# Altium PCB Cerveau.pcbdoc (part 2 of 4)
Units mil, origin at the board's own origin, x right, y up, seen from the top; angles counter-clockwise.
Board outline 3985.6 x 3546.5 mil, 2 copper layers (Top Layer, Bottom Layer), stack 62.2 mil thick; 170 components, 173 nets, 734 pads, 576 vias.
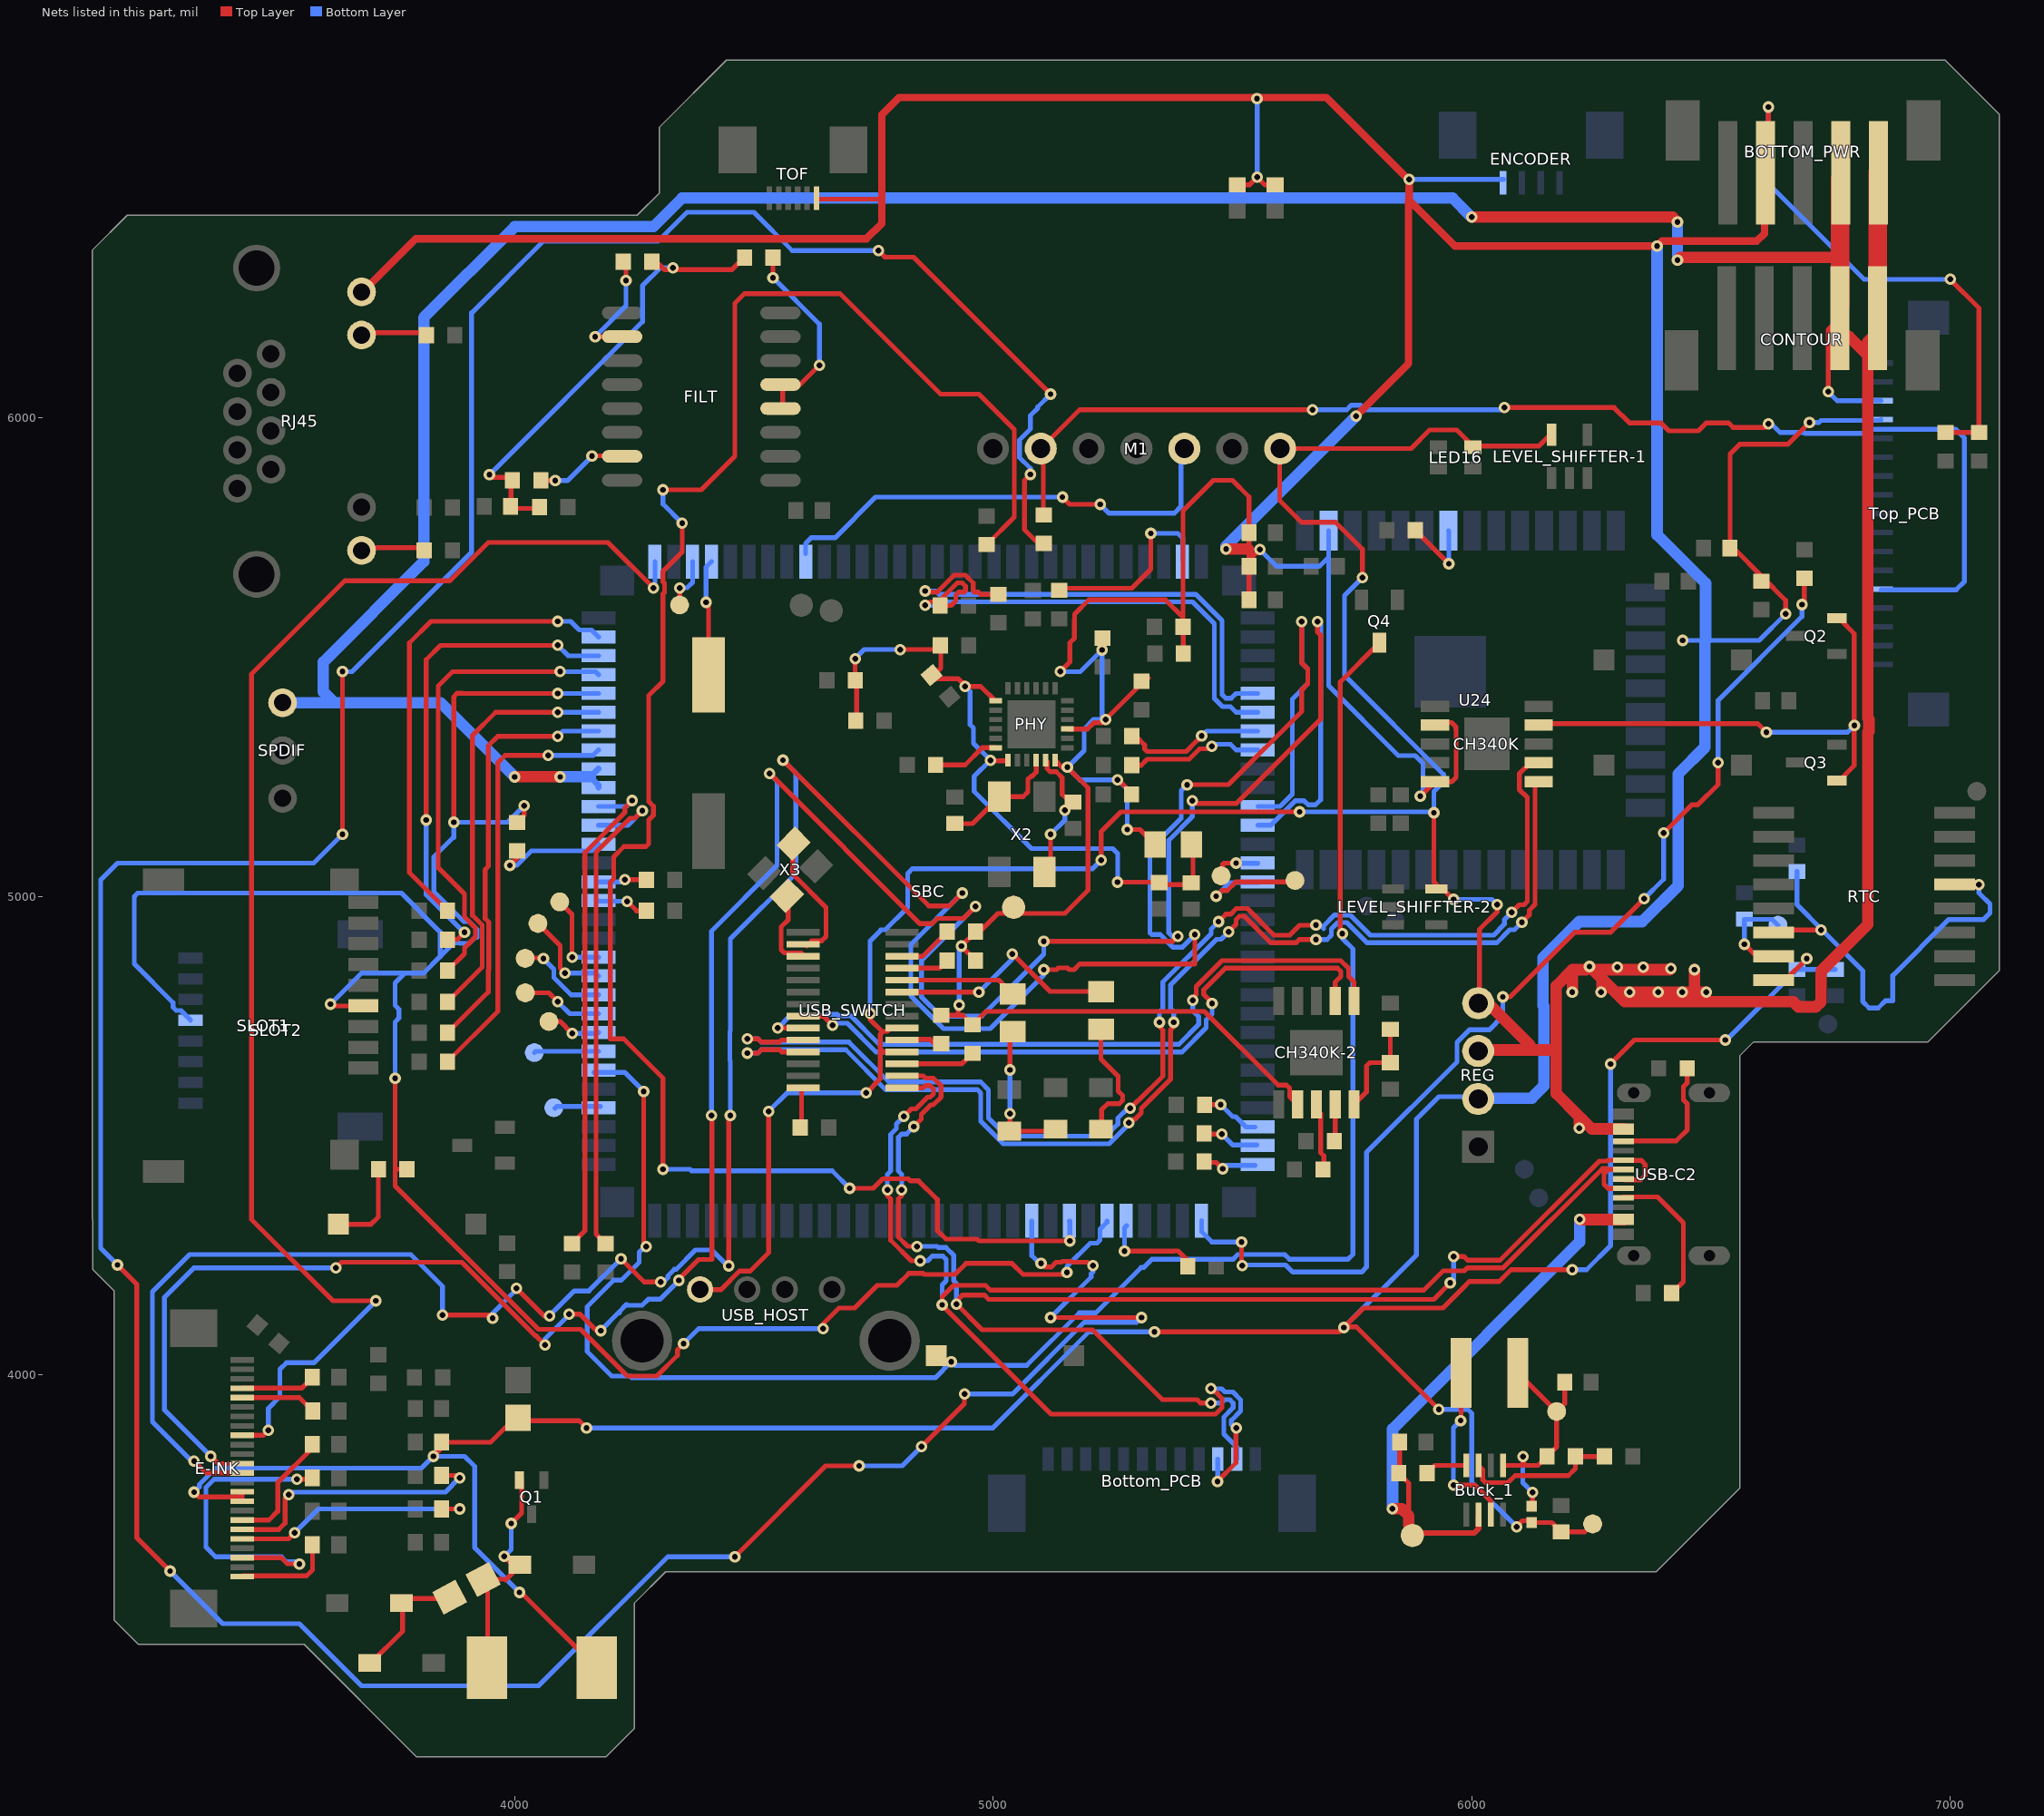
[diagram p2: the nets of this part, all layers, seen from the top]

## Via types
v1: diameter 24, hole 12, Top Layer to Bottom Layer, 576 vias

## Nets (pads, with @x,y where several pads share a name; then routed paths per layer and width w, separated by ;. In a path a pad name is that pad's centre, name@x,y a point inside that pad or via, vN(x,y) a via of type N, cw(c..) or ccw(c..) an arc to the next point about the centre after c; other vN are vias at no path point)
3V3: 3V3.1 BOTTOM_PWR.2 C7.1 C8.2 C9.1 C10.2 C11.1 C18.2 C28.1 C29.2 C33.2 C35.1 C36.2 CH340K-2.7 CH340K.7 CH340K.10 E-INK.15 E-INK.16 ENCODER.1 L2.2 L3.1 P-SCL.2 P-SDA.2 PHY.6 PHY.9 R9.1 R10.1 R11.2 R12.2 R13.2 R14.2 R15.2 R16.2 R21.2 R32.2 R41.2 REG.2 RJ45.9 RSC_3V3.1 RTC.16 TOF.1 Top_PCB.14 U24.2 | length 20598.6
  Top Layer w10: v1(3330,3755) 3340,3745 3421.8,3745 E-INK.15@3430.7,3753.9 ; E-INK.16@3430.7,3736.1 E-INK.15@3430.7,3753.9 ; E-INK.15@3430.7,3755.8 E-INK.15@3430.7,3753.9 ; v1(3830,3830) 3847.6,3847.6 C18.2@3847.6,3857.6 ; C18.2@3847.6,3859.4 C18.2@3847.6,3860 ; C18.2@3848.2,3859.4 3949.7,3859.4 C33.2@3998.4,3908.1 ; C33.2@4002.3,3904.3 4134.7,3904.3 v1(4150.1,3888.9) ; v1(4010,3545.4) 4013.1,3545.4 L3.1@4160.3,3398.2 ; TOF.1@4630.2,6457.7 4762.1,6457.7 4763.8,6459.4 ; R15.2@4891.5,4751.7 4926.4,4751.7 ; v1(4928.8,4773) 4926.4,4770.6 4926.4,4751.7 ; R14.2@4963.2,4866.3 4963.2,4866.6 v1(4933.5,4896.3) 4963.2,4926 R13.2@4963.2,4926.3 4971.8,4926.3 5010.2,4964.7 5019,4964.7 ; 3V3.1@5042.7,4997.2 5047.1,4992.8 5019,4964.7 ; PHY.6@5129.2,5284.9 5144.1,5270 v1(5155,5270) 5198.1,5226.9 5198.1,5013.1 5149.7,4964.7 5019,4964.7 ; v1(5140,5470) 5160,5490 5160,5530 5169.8,5539.8 5169.8,5578.4 5170,5578.6 5170,5590 5200,5620 5360,5620 5396.5,5583.5 ; PHY.9@5155.1,5350.2 5155.3,5350 5196.9,5350 5209.9,5363 5228,5363 v1(5235,5370) 5310,5445 R10.1@5310,5449.7 ; v1(5227.4,5515.4) 5228.2,5516.2 R41.2@5228.2,5545.3 ; v1(5259.9,5244) 5261.3,5244 R9.1@5292.3,5213 ; v1(5280,5140) 5306.9,5140 L2.2@5338.3,5108.6 ; R10.1@5319.5,5461.5 R10.1@5324.3,5456.7 ; v1(5337,4090) 5723.7,4090 v1(5732.6,4099) 5773.7,4140 5940,4140 5981.6,4181.6 5981.6,4181.8 5995,4195.2 6057.1,4195.2 6081.9,4220 v1(6210,4220) ; R12.2@5397,5507.8 5397,5563.2 R11.2@5396.5,5563.8 5396.5,5583.5 ; C7.1@5510,6487.6 5535.9,6487.6 v1(5551.7,6503.4) 5567.6,6487.4 C8.2@5589.2,6487.4 ; C9.1@5534.7,5620.3 C10.2@5534.7,5690.3 ; v1(5557.2,5725.3) 5534.7,5702.7 C11.1@5534.7,5760.3 5534.7,5835.3 5500,5870 5460,5870 5396.5,5806.5 5396.5,5583.5 ; CH340K-2.7@5636,4565.3 5619.5,4581.9 5619.5,4599.4 5613,4605.8 5595.5,4605.8 5441.4,4760 4984.8,4760 R16.2@4956.5,4731.7 4936.5,4751.7 4926.4,4751.7 ; v1@5735.1,4100.4 5758.8,4100.4 v1(5931.2,3928) ; v1(5892.6,5209.4) 5917.2,5233.9 CH340K.10@5917.2,5239.1 ; CH340K.7@5918.4,5363.7 5957.7,5363.7 5967.1,5354.3 ; CH340K.10@5926.7,5239.7 5957.7,5239.7 5967.2,5249.2 5967.2,5349.4 5967.2,5354.2 5967.1,5354.3 ; 5967.1,5349.4 5967.1,5354.3 ; v1(6093.7,3682.7) 6106,3695.1 R32.2@6123.9,3695.1 ; R32.2@6125.1,3691.5 6167.5,3691.5 C29.2@6186.9,3672 6236.1,3672 RSC_3V3.1@6252.7,3688.6 ; v1(6290,4650) 6340,4700 v1(6530,4700) ; C28.1@6539.3,5727.9 6540,5728.6 6540,5925 6560,5945 6660.1,5945 v1(6705.8,5990.7) ; C28.1@6550,5725.6 R21.2@6607.6,5668 ; R21.2@6608.8,5666.2 6656.1,5618.9 v1(6656.1,5590.7) ; BOTTOM_PWR.2@6613.8,6512.6 6620,6518.7 v1(6620,6650) ; RTC.16@6631,4825 6655,4825 v1(6700,4870) ; P-SCL.2@6990,5969.7 P-SDA.2@7060,5969.7 7060,6230 v1(7000,6290)
  Top Layer w15.7: RJ45.9@3681.1,6262.5 3793.4,6374.8 4735.4,6374.8 4767.1,6406.5 4767.1,6634.2 4803,6670.1 5696,6670.1 5869,6497.1 5869,6455.3 5964.8,6359.5 v1(6387.4,6359.5) 6397.8,6370 6596,6370 6611.8,6385.7 BOTTOM_PWR.2@6611.8,6489 ; v1(5758.1,6003.9) 5868,6113.8 5868,6454.9
  Top Layer w23.6: v1(5486.6,5726.1) 5532.5,5726.1 5533.4,5725.2
  Bottom Layer w10: v1(3330,3755) 3341,3766 3341,3770.8 3375.2,3805.1 3805.1,3805.1 v1(3830,3830) 3895.3,3830 3916.7,3808.6 3916.7,3638.6 v1(4010,3545.4) ; v1(4150.1,3888.9) 4998.9,3888.9 5200,4090 v1(5337,4090) ; v1(4928.8,4773) 4928.8,4891.6 v1(4933.5,4896.3) ; v1(5140,5470) 5182,5470 v1(5227.4,5515.4) 5227.4,5377.5 v1@5233.3,5371.6 ; v1(5235,5370) 5210,5370 5190,5350 5190,5305 v1(5155,5270) 5181,5244 v1(5259.9,5244) 5280,5223.9 v1(5280,5140) ; v1(5551.3,6667.5) 5551.7,6667 v1(5551.7,6503.4) ; v1(5557.2,5725.3) 5592.2,5690.3 5682.2,5690.3 5701.1,5709.2 U24.2@5701.1,5764.6 ; 5700.8,5707.9 5700.8,5440.3 5846.5,5294.6 5881.8,5294.6 5898,5278.4 5898,5214.7 v1(5892.6,5209.4) ; v1(5732.6,4099) 5884.6,4251 5884.6,4534.9 5931.6,4581.8 REG.2@6007.1,4581.8 ; v1(5869.3,6499.1) ENCODER.1@6066.8,6499.1 ; v1(5931.2,3928) 5992,3928 6000,3920 6000,3776.4 v1(6093.7,3682.7) ; v1(6210,4220) 6240,4220 6290,4270 v1(6290,4650) ; v1(6440.8,5535.2) 6488.7,5535.2 6600.6,5535.2 v1(6656.1,5590.7) ; v1(6530,4700) 6532.4,4700 C36.2@6680,4847.6 ; v1(6620,6650) 6620,6490 6820,6290 v1(7000,6290) ; v1(6700,4870) 6700,4867.6 C36.2@6680,4847.6 ; v1(6705.8,5990.7) 6725.7,5990.7 6730,5995 6853.4,5995 Top_PCB.14@6855.3,5996.9 ; C35.1@6760,4847.6 C36.2@6680,4847.6
  Bottom Layer w23.6: v1(5486.6,5726.1) 5486.6,5732.3 v1(5758.1,6003.9)
  Bottom Layer w24.1: REG.2@6007.1,4579.4 6008.1,4578.4 6126.2,4578.4 ; 6126.2,4579.5 6150.8,4604.1 6150.8,4770.3 ; 6148.9,4772.1 6148.9,4871.6 6224.8,4947.5 6356.2,4947.5 6431.6,5022.9 6431.6,5256.2 6487.3,5311.9 6487.3,5533.1 ; v1(6387.4,6359.5) 6387.4,5755.8 6488.7,5654.5 6488.7,5535.2
3V3_MOD: R22.2 R45.2 SBC.66 SBC.116 SLOT1.4 SLOT2.4 | length 4873.3
  Top Layer w10: v1(3615,4775) 3618.7,4771.3 SLOT1.4@3683.7,4771.3 ; v1(3750,4620) 3750,4429 ; R22.2@3774.7,4430 3751,4430 3750,4429 ; v1(3872.9,5155) 3872.9,5417.9 3880,5425 3890,5425 3890.6,5424.4 v1(4090,5424.4) ; R45.2@4005,5154.7 4020,5169.7 v1(4020,5190) ; 4049.6,4095.4 3750,4395 3750,4429 ; 4049.6,4095.5 4137.7,4095.5 4235.7,3997.5 4296.9,3997.5 4340.3,4040.9 4340.3,4052.8 v1(4352.9,4065.5) ; v1(4644.4,4096.8) 4644.4,4106.7 4677.6,4140 4710.1,4140 4757.5,4187.4 4798.8,4187.4 4823.6,4212.2 4853.4,4212.2 4855.6,4210 4920,4210 4943,4233 5039.5,4233 5062.5,4210 5149.6,4210 v1(5154,4214.4)
  Bottom Layer w10: SLOT2.4@3322.7,4741.5 3302.4,4761.8 3292.6,4761.8 3286.1,4768.3 3286.1,4778.1 3205,4859.2 3205,5000 3212.1,5007.1 3763.2,5007.1 3844.3,4926 3844.3,4874.3 ; v1(3615,4775) 3680,4840 3770.7,4840 ; v1(3750,4620) 3750,4737.5 3758,4745.5 3758,4764.5 3750,4772.5 3750,4819.3 3770.7,4840 ; 3871.9,5123.5 3831.2,5082.9 3831.2,5010.1 3893.3,4948 3904.5,4948 3921.3,4931.2 3921.3,4914.7 ; 3872.9,5123.5 v1(3872.9,5155) 3985,5155 v1(4020,5190) ; 3918,4915.5 3904.5,4902 3885.5,4902 3884.6,4902.9 3872.9,4902.9 3844.3,4874.3 ; v1(4090,5424.4) SBC.116@4175,5424.4 ; v1(4352.9,4065.5) 4384.3,4096.8 v1(4644.4,4096.8) ; v1(5154,4214.4) 5154,4226.8 5202.8,4275.6 5217,4275.6 5223.4,4282.1 5223.4,4305 5238,4319.6 SBC.66@5238,4322 ; 3770.7,4840 3810,4840 3844.3,4874.3
5V: 5V.1 BOTTOM_PWR.4 BOTTOM_PWR.5 Buck_1.2 C31.1 CONTOUR.1 CONTOUR.2 LED16.4 LEVEL_SHIFFTER-1.5 LEVEL_SHIFFTER-2.5 M1.7 R29.1 REG.3 REG.4 SBC.111 SBC.112 SPDIF.3 Top_PCB.15 USB-C2.A4B9 USB-C2.B4A9 USB_HOST.1 USB_SWITCH.18 USB_SWITCH.20 | length 14819.2
  Top Layer w10: USB_HOST.1@4387.5,4178.5 4431.4,4178.5 4469.9,4217 4492,4217 4530.7,4255.7 v1(4530.7,4551) ; v1(4734.7,4589.4) 4763.8,4618.5 4763.8,4681.9 ; v1(4742.8,4755.6) 4742.8,4742.6 4768.8,4716.6 ; USB_SWITCH.20@4786.7,4726 4778.8,4718 4770.2,4718 4768.8,4716.6 ; USB_SWITCH.18@4811.1,4674.6 4771.1,4674.6 4763.8,4681.9 ; v1(5225.8,5076.1) 5225.8,5135.8 5266.9,5176.9 v1(5640.4,5176.9) ; v1(5771.4,5666.4) 5771.4,5726.3 5715.5,5782.2 5644.1,5782.2 5598.5,5827.8 5598.5,5936.3 5873.5,5936.3 5912,5974.9 5968.8,5974.9 LED16.4@6002.6,5941.1 ; R29.1@5849.4,3796.7 C31.1@5849.4,3859.6 ; R29.1@5849.9,3792 5868.5,3773.4 5868.5,3705.4 ; 5V.1@5868.5,3686.4 5875.5,3679.4 5V.1@5875.5,3672.7 ; v1(5921,5174.9) 5921,5030.6 LEVEL_SHIFFTER-2.5@5933.7,5018 ; LEVEL_SHIFFTER-2.5@5941.9,5014 v1(5961.9,4994) ; LED16.4@6007.4,5941.2 6139.8,5941.2 LEVEL_SHIFFTER-1.5@6164.7,5966.1 ; REG.4@6016.2,4776.5 6016.2,4780.1 6016.2,4931.2 6053.3,4968.3 v1(6053.3,4983.1) ; v1(6745,6055) 6745,6184.7 CONTOUR.2@6769.2,6208.9 ; 4763.8,4681.9 4763.8,4711.6 4768.8,4716.6
  Top Layer w11.8: 5V.1@5883.5,3663.9 5889.4,3669.9 6004.7,3669.9 ; 6005.6,3670.4 6014.1,3679 Buck_1.2@6014.1,3706.1
  Top Layer w23.6: v1(4000,5250) v1(4095,5250) ; v1(6000,6420) 6420,6420 v1(6430,6410) ; v1(6430,6330) 6435.9,6335.9 6769.7,6335.9
  Top Layer w24.1: v1(5834.5,3720.3) 5853.6,3720.3 5868.5,3705.4 5V.1@5868.5,3686.4 ; REG.4@6009,4780.1 REG.4@6016.2,4780.1 ; REG.3@6016.6,4680.2 6017.6,4679.3 6176.6,4679.3 ; REG.4@6030.9,4780.1 6121.3,4689.7 ; v1(6210,4800) 6210.5,4800.5 6210.5,4846.9 ; v1@6224.8,4517 6224.8,4539.8 6176.6,4588 6176.6,4679.3 ; v1(6225.5,4325) 6226.1,4324.5 USB-C2.A4B9@6319.3,4324.5 ; 6229.9,4535.3 6251,4514.1 USB-C2.B4A9@6318.1,4514.1 ; v1(6246.2,4853.8) 6239.3,4846.9 6210.5,4846.9 ; v1(6270,4800) 6272.4,4802.4 6272.4,4827.6 ; v1(6304.6,4852.1) v1@6309.8,4846.9 ; v1(6358.3,4852.5) v1@6363.9,4846.9 ; v1(6416.2,4849.1) 6414,4846.9 v1@6363.9,4846.9 ; v1(6465.3,4847) 6465.3,4801.2 6464.1,4800 ; v1(6490,4800) 6464.1,4800 ; CONTOUR.2@6772.3,6170.4 6788.4,6170.4 6821.7,6137.1 ; 6827.4,6137.1 6827.4,5372.5 6829.9,5370.1 6829.9,5345.2 6827.4,5342.8 6827.4,4941.1 6730,4843.6 6730,4780 6719.3,4769.3 6682.6,4769.3 6671.8,4780 6320,4780 6300,4800 ; 6827.4,6159 CONTOUR.1@6851.2,6182.8 ; 6176.6,4679.3 6176.6,4813 6210.5,4846.9 ; 6272.4,4827.6 6253.1,4846.9 v1@6309.8,4846.9 ; 6272.4,4827.6 6300,4800 ; 6300,4800 v1(6330,4800) v1(6390,4800) v1(6440,4800) 6464.1,4800 ; v1@6309.8,4846.9 v1@6363.9,4846.9
  Top Layer w39.4: CONTOUR.2@6769.7,6235.2 6769.7,6335.9 BOTTOM_PWR.4@6769.7,6499.7 ; CONTOUR.1@6848.4,6192.7 BOTTOM_PWR.5@6848.4,6515
  Bottom Layer w10: v1(4530.7,4551) 4569.1,4589.4 v1(4734.7,4589.4) ; v1(4742.8,4755.6) 4742.8,4907.1 4766.2,4930.5 ; 4765.1,4930.5 4766.2,4930.5 ; 4821,4977.2 4774.3,4930.5 4766.2,4930.5 ; 4821.2,4977 4821.2,5048.1 4831.2,5058.1 5207.9,5058.1 v1(5225.8,5076.1) ; v1(5640.4,5176.9) 5919,5176.9 v1(5921,5174.9) 5921,5219.6 5941.3,5239.8 5941.3,5254.9 5734,5462.2 5734,5629 v1(5771.4,5666.4) ; v1(5961.9,4994) 6042.4,4994 v1(6053.3,4983.1) ; v1(6745,6055) 6763.8,6036.2 Top_PCB.15@6855.3,6036.2
  Bottom Layer w12.6: SBC.111@4175,5227.6 4175,5233.1 4158.1,5250 SBC.112@4175,5266.9
  Bottom Layer w23.6: SPDIF.3@3515,5405 3622.7,5405 ; v1(4000,5250) 3845,5405 3622.7,5405 ; v1(4095,5250) 4158.1,5250 ; v1(6000,6420) 5960,6460 4350,6460 4290,6400 4000,6400 3810,6210 3810,5700 3600,5490 3600,5427.7 3622.7,5405 ; v1(6430,6330) v1(6430,6410)
  Bottom Layer w24.1: v1(5834.5,3720.3) 5834.5,3887 6225.5,4278 v1(6225.5,4325)
  other v1: 6224.7,4515.7
$1N2333: R2.2 USB-C2.A5 | length 304.6
  Top Layer w10: USB-C2.A5@6316.7,4371.9 6388.1,4371.9 6442.1,4317.9 6442.1,4195.1 R2.2@6418.1,4171
$1N2334: R1.2 USB-C2.B5 | length 272.3
  Top Layer w10: USB-C2.B5@6323,4489.1 6427.3,4489.1 6450.6,4512.4 6450.6,4566.6 6442.1,4575 6442.1,4602.2 6450.6,4610.7 R1.2@6450.6,4640.4
$1N52006: Buck_1.3 L1.1 | length 361.4
  Top Layer w10: v1(5961.9,3769.6) 6006.9,3769.6 6039.7,3736.8 Buck_1.3@6039.7,3708.4 ; v1(5976.9,3904.6) 5977.9,3905.5 L1.1@5977.9,4004.6
  Bottom Layer w10: v1(5961.9,3769.6) 5961.9,3889.6 v1(5976.9,3904.6)
$1N52007: Buck_1.5 C30.1 L1.2 R30.2 R32.1 REG_OUT.1 | length 519.8
  Top Layer w10: Buck_1.5@6065.3,3810.8 6113.3,3810.8 ; L1.2@6096,4004.6 6176.9,3923.6 REG_OUT.1@6177.5,3923.6 ; v1(6106.9,3829.6) 6106.9,3817.2 6113.3,3810.8 ; R32.1@6125.1,3725.5 6126.9,3727.4 v1(6126.9,3754.6) ; C30.1@6194.4,3984.6 6194.4,3940.5 REG_OUT.1@6177.5,3923.6 ; 6113.3,3810.8 6138.4,3810.8 R30.2@6157.3,3829.6 6177.5,3849.8 REG_OUT.1@6177.5,3923.6
  Bottom Layer w10: v1(6106.9,3829.6) 6106.9,3774.6 v1(6126.9,3754.6)
$1N52011: Buck_1.7 R30.1 R31.1 | length 327.9
  Top Layer w10: Buck_1.7@6014.1,3810.8 6022.8,3802.1 6022.8,3781.2 6029.3,3774.8 6075.8,3774.8 6090.6,3789.6 6201.9,3789.6 6216.6,3804.2 R30.1@6216.6,3829.6 R31.1@6277.3,3829.6
$1N52013: Buck_1.8 R29.2 | length 88.6
  Top Layer w10: R29.2@5906.6,3794.6 5922.8,3810.8 Buck_1.8@5988.5,3810.8
$1N100879: FILT.4 FILT.5 R33.1 | length 408
  Top Layer w10: v1(4539.8,6293.3) 4539.8,6326.9 R33.1@4541.4,6328.5 ; FILT.5@4553.6,6065.6 FILT.5@4560,6065.6 ; FILT.4@4560,6018.4 FILT.5@4560,6065.6 ; v1(4636.9,6110.4) 4592.1,6065.6 FILT.5@4560,6065.6
  Bottom Layer w10: v1(4539.8,6293.3) 4636.9,6196.2 v1(4636.9,6110.4)
$1N101081: FILT.15 R34.1 | length 178.7
  Top Layer w10: R34.1@4054.8,5870.3 4055.9,5869.2 v1(4084.7,5869.2) ; v1(4161.5,5920.4) 4162,5920.9 FILT.15@4211.6,5920.9
  Bottom Layer w10: v1(4084.7,5869.2) 4110.3,5869.2 v1(4161.5,5920.4)
$1N101084: FILT.10 R35.1 | length 230.9
  Top Layer w10: v1(4168,6170) 4211.9,6170 FILT.10@4213.4,6168.5 ; R35.1@4223.8,6324.5 4232.6,6315.7 v1(4232.6,6287.7)
  Bottom Layer w10: v1(4168,6170) 4232.6,6234.6 v1(4232.6,6287.7)
$1N101107: C26.2 R33.2 R34.2 R35.2 R36.2 | length 969.8
  Top Layer w10: v1(3947.3,5881.5) 3953,5875.8 R34.2@3994,5875.8 ; R34.2@3992.3,5867.1 3992.3,5817.5 3998.7,5811.1 R36.2@4056.3,5811.1 ; R35.2@4298.4,6324.9 4313.4,6310 v1@4334.8,6310 ; v1(4330.8,6314) v1@4334.8,6310 ; R33.2@4475.4,6331.6 4453.8,6310 v1@4334.8,6310
  Bottom Layer w10: v1(3947.3,5881.5) 4267,6201.2 4267,6276.4 4304.6,6314 v1(4330.8,6314)
$1N108144: R24.2 RJ45.10 | length 132.5
  Top Layer w10: RJ45.10@3686.9,6178.4 3817.7,6178.4 R24.2@3818.9,6177.2
$1N108803: PHY.24 R7.2 | length 140
  Top Layer w10: R7.2@4879.7,5275 4941.3,5275 4977.1,5310.8 PHY.24@5004.9,5310.8
$1N111794: R25.1 RJ45.12 | length 129.9
  Top Layer w10: RJ45.12@3680.8,5715.3 3694.7,5729.2 R25.1@3804.9,5729.2
$1N122388: C23.1 E-INK.22 | length 689.9
  Top Layer w10: E-INK.22@3430.7,3618 3512,3618 3525,3605 v1(3550,3605) ; v1(3545,3782.1) 3574.5,3782.1 C23.1@3577.4,3785
  Bottom Layer w10: v1(3545,3782.1) 3372.1,3782.1 3355,3765 3355,3640 3375,3620 3512.5,3620 3523,3609.5 3545.5,3609.5 v1(3550,3605)
$1N122658: C32.2 L3.2 Q1.2 U21.2 | length 502.2
  Top Layer w10: L3.2@3935.8,3383.6 3943.4,3391.2 C32.2@3943.4,3573.1 ; C32.2@3943.4,3584.1 C32.2@3943.4,3573.1 ; v1(3978.3,3620.6) 3992.8,3606 U21.2@4013.4,3606 ; 3979.5,3573.1 C32.2@3943.4,3573.1 ; 3980.7,3571.4 U21.2@4011.8,3602.5 ; v1(3992.8,3689.5) 4014.7,3711.3 Q1.2@4014.7,3782.8
  Bottom Layer w10: v1(3978.3,3620.6) 3992.8,3635.1 v1(3992.8,3689.5)
$1N122770: C32.1 U22.2 U23.1 | length 259.9
  Top Layer w10: U22.2@3697.9,3396.3 3765.8,3464.2 U23.1@3765.8,3524.4 ; U23.1@3763.5,3523 3773.3,3532.8 C32.1@3863.1,3532.8
$1N123105: C16.2 E-INK.4 | length 156.1
  Top Layer w10: E-INK.4@3430.7,3972.3 3554.8,3972.3 C16.2@3577.4,3995
$1N123149: C17.2 E-INK.5 | length 158.6
  Top Layer w10: E-INK.5@3430.7,3952.6 3549.8,3952.6 C17.2@3577.8,3924.7
$1N123431: C25.1 E-INK.24 | length 205
  Top Layer w10: E-INK.24@3430.7,3578.6 3432.1,3580 3565,3580 3577.4,3592.4 C25.1@3577.4,3645
$1N123445: C21.1 E-INK.20 | length 517.6
  Top Layer w10: E-INK.20@3430.7,3657.4 3527.4,3657.4 v1(3540,3670) ; C21.1@3847.6,3720 v1(3885,3720)
  Bottom Layer w10: v1(3540,3670) 3590,3720 v1(3885,3720)
$1N123447: C20.1 E-INK.19 | length 576.1
  Top Layer w10: E-INK.19@3430.7,3677 3507,3677 3520,3690 3520,3742.1 v1(3527.9,3750) ; C20.1@3847.6,3790 3880,3790 v1(3885,3785)
  Bottom Layer w10: v1(3527.9,3750) 3527.9,3752.1 3525,3755 3855,3755 v1(3885,3785)
$1N123450: C19.1 E-INK.18 | length 251.9
  Top Layer w10: E-INK.18@3430.7,3696.7 3486.7,3696.7 3504.9,3714.9 3504.9,3774.9 3577.4,3847.4 C19.1@3577.4,3855
$1N137689: C5.2 PHY.4 X2.3 | length 254.8
  Top Layer w10: C5.2@4920,5152.4 4956.5,5152.4 X2.3@5012.8,5208.7 5062.6,5208.7 5072.6,5218.7 5072.6,5244.8 5079.1,5251.2 5081.2,5251.2 5090,5260 5090,5284.7 PHY.4@5089.8,5284.9
$1N137708: C6.1 PHY.5 X2.1 | length 291.3
  Top Layer w10: X2.1@5107.2,5051.3 5120,5064 v1(5120,5130) ; PHY.5@5109.5,5284.9 5112.7,5281.7 5112.7,5267.3 5119.1,5260.8 5131.7,5260.8 5144.2,5248.3 5144.2,5213.3 C6.1@5163.2,5194.1 ; v1(5150,5180) 5166.7,5196.7 C6.1@5166.7,5197.6
  Bottom Layer w10: v1(5120,5130) 5150,5160 v1(5150,5180)
$1N182029: R19.2 USB_SWITCH.14 | length 83.2
  Top Layer w10: R19.2@4599.4,4517.1 4599.4,4595.9 USB_SWITCH.14@4602.5,4599
$1N186429: USB_SWITCH.3 X3.3 | length 172.8
  Top Layer w10: X3.3@4571.7,4999.7 4571.7,4951.2 4557,4936.6 4557,4888.7 4563.4,4882.3 4599,4882.3 USB_SWITCH.3@4606.8,4874.5
$1N186434: USB_SWITCH.2 X3.1 | length 264.1
  Top Layer w10: X3.1@4580.9,5103.7 4580.9,5046.7 4650.5,4977.2 4650.5,4916.2 4641.5,4907.3 4621,4907.3 USB_SWITCH.2@4610.7,4897
$1N186463: C3.1 C4.2 L2.1 PHY.1 PHY.19 R3.1 R4.1 R5.2 R6.2 | length 1510.9
  Top Layer w10: R6.2@4710.3,5366.4 4714.8,5371 R3.1@4714.8,5452.3 ; R3.1@4711.2,5451.1 4711.2,5493.9 v1@4713.4,5496.2 ; v1(4805.5,5516.1) 4876.4,5516.1 R4.1@4890.6,5530.4 ; R4.1@4890.3,5529.6 4890.3,5477.5 4868.2,5455.4 4926.3,5455.4 v1@4940.4,5441.3 ; v1@4940.4,5446.7 v1@4940.4,5441.3 ; v1@4941.1,5439.1 4974.1,5439.1 PHY.19@5003.2,5410 ; v1@4941.1,5440.6 v1@4940.4,5441.3 ; v1(4994.2,5284.7) 4995.3,5283.6 PHY.1@5031.3,5283.6 ; v1(5260,5030) 5346.3,5030 C3.1@5347.2,5029.1 ; C3.1@5347.2,5024.7 5404.9,5024.7 C4.2@5409.9,5029.8 ; C4.2@5410,5029.8 5417.5,5037.1 L2.1@5417.5,5110
  Bottom Layer w10: v1(4711.6,5497.1) 4730.6,5516.1 v1(4805.5,5516.1) ; v1(4941.3,5439.1) 4951.7,5428.7 4951.7,5359.4 4958.6,5352.5 4958.6,5320.3 v1(4994.2,5284.7) 4960,5250.6 4960,5220 5080,5100 5250,5100 5260,5090 v1(5260,5030)
$1N186835: CH340K-2.8 R-RX2.1 | length 136.7
  Top Layer w10: CH340K-2.8@5674.5,4556.1 5684.5,4546.1 5684.5,4464.3 5691.1,4457.8 R-RX2.1@5691.1,4426.3
$1N186841: CH340K-2.9 R-TX2.1 | length 79
  Top Layer w10: R-TX2.1@5714.8,4484.8 5714.8,4560.9 CH340K-2.9@5716.9,4562.9
$1N186854: C1.2 C2.1 CH340K-2.10 | length 213.7
  Top Layer w10: CH340K-2.10@5754.1,4565.3 5780,4591.2 5780,4645.5 5787.1,4652.6 C1.2@5830,4652.6 C2.1@5830,4722.4
$1N187062: R16.1 USB_SWITCH.17 | length 156.5
  Top Layer w10: USB_SWITCH.17@4809.2,4650.1 4934.3,4650.1 R16.1@4956.5,4672.3
$1N187101: R13.1 USB_SWITCH.26 | length 115.8
  Top Layer w10: USB_SWITCH.26@4809.2,4875.1 4852.7,4875.1 R13.1@4903.8,4926.3
$1N187435: R15.1 USB_SWITCH.19 | length 86.5
  Top Layer w10: USB_SWITCH.19@4809.2,4700.1 4810.4,4701.3 4868.5,4701.3 4877.5,4692.3 R15.1@4891.5,4692.3
$1N187580: R14.1 USB_SWITCH.25 | length 101.3
  Top Layer w10: USB_SWITCH.25@4809.2,4850.1 4887.7,4850.1 R14.1@4903.8,4866.3
$1N187585: R18.1 USB_SWITCH.24 | length 243.2
  Top Layer w10: USB_SWITCH.24@4809.2,4825.1 5011.8,4825.1 R18.1@5040.5,4796.4
$1N187593: R17.2 USB_SWITCH.23 | length 487.8
  Top Layer w10: USB_SWITCH.23@4809.2,4800.1 v1(4970,4800.1) ; v1(5040,4880) 5118.6,4801.4 R17.2@5225.5,4801.4
  Bottom Layer w10: v1(4970,4800.1) 5040,4870.1 v1(5040,4880)
$1N196349: PORT-1.1 PORT-3.2 R18.2 | length 307.8
  Top Layer w10: v1(5035.2,4546.2) 5035.2,4509.5 PORT-3.2@5131.3,4509.5 ; v1(5035.2,4637.6) 5035.2,4716 R18.2@5038.9,4719.7
  Bottom Layer w10: v1(5035.2,4546.2) v1(5035.2,4637.6)
$1N196355: PORT-2.1 R17.1 | length 254.6
  Top Layer w10: R17.1@5225.3,4721.7 5225.3,4660.4 5261.1,4624.6 5261.1,4593.3 5270.5,4583.9 5270.5,4573.9 5263.5,4566.8 5239.2,4566.8 5226.3,4553.9 PORT-2.1@5226.3,4518.3
$1N217183: R20.2 U24.7 | length 169.1
  Top Layer w10: R20.2@5881.9,5765.3 5951.9,5695.3 v1(5952.2,5695.3)
  Bottom Layer w10: U24.7@5951.1,5764.6 5952.2,5763.5 v1(5952.2,5695.3)
$1N235786: R47.1 SBC.106 | length 102.1
  Top Layer w10: v1(4230,5035) R47.1@4275.3,5035
  Bottom Layer w10: SBC.106@4175,5030.7 4225.7,5030.7 v1(4230,5035)
$1N235788: R46.1 SBC.105 | length 109.1
  Top Layer w10: v1(4235,4990) 4255,4970 R46.1@4275.3,4970
  Bottom Layer w10: SBC.105@4175,4991.3 4176.3,4990 v1(4235,4990)
$1N236245: GPIO0_A1.1 SBC.3 | length 110.7
  Top Layer w10: GPIO0_A1.1@4344.7,5609.4 4344.7,5644.7 v1(4345,5645)
  Bottom Layer w10: v1(4345,5645) 4360,5645 4371.9,5656.9 SBC.3@4371.9,5700
$1N236288: SBC.101 TP5.1 | length 199.6
  Top Layer w10: TP5.1@4048.5,4943.7 4095,4897.2 4095,4850 v1(4105,4840)
  Bottom Layer w10: v1(4105,4840) 4168.9,4840 SBC.101@4175,4833.9
$1N236290: SBC.102 TP6.1 | length 181.3
  Top Layer w10: TP6.1@4094.1,4988.7 4120,4962.9 v1(4120,4873.2)
  Bottom Layer w10: v1(4120,4873.2) SBC.102@4175,4873.2
$1N236292: SBC.100 TP4.1 | length 187.9
  Top Layer w10: TP4.1@4024.5,4871.5 4055,4871.5 v1@4055.6,4872.2
  Bottom Layer w10: v1(4060,4870) 4082,4848 4082,4830.5 4118,4794.5 SBC.100@4175,4794.5
$1N236294: SBC.99 TP3.1 | length 170.9
  Top Layer w10: TP3.1@4022.2,4798.7 4071.3,4798.7 v1(4090,4780)
  Bottom Layer w10: v1(4090,4780) 4114.9,4755.1 SBC.99@4175,4755.1
$1N236296: SBC.98 TP2.1 | length 114.6
  Top Layer w10: TP2.1@4071.6,4738.7 4095,4738.7 v1(4120,4713.7)
  Bottom Layer w10: v1(4120,4713.7) 4173,4713.7 SBC.98@4175,4715.7
$1N236298: SBC.97 TP1.1 | length 135.1
  Bottom Layer w10: TP1.1@4041,4673.7 4043.6,4676.4 SBC.97@4175,4676.4
$1N236312: Q4.3 RST_CMPT.1 SBC.96 | length 3831.5
  Top Layer w10: v1(4269.6,4592.8) 4269.6,4273.9 v1(4274.9,4268.6) ; RST_CMPT.1@4881.3,4040 4893.5,4027.8 v1(4912.3,4027.8) ; v1(5729.6,4922.5) 5725.3,4926.8 5725.3,5448.6 Q4.3@5807.2,5530.5
  Bottom Layer w10: SBC.96@4165.4,4632.5 4229.9,4632.5 v1(4269.6,4592.8) ; v1@4273.5,4269.6 4260.2,4256.4 4260.2,4235.2 4223.2,4198.2 4206.8,4198.2 4151.5,4142.9 4151.5,4048.7 4202.7,3997.5 4241.4,3997.5 4244.7,3994.2 4878.8,3994.2 v1(4912.3,4027.8) 4920.1,4020 5070,4020 5180,4130 5214.5,4130 5309,4224.5 5314.5,4224.5 5332,4242 5501.6,4242 5511,4251.5 5609.4,4251.5 5618.9,4242 5741.7,4242 5751.7,4252 5751.7,4890.4 5729.6,4912.5 v1(5729.6,4922.5)
$1N245340: R45.1 SBC.108 | length 239.9
  Top Layer w10: v1(3990,5065) 4005,5080 R45.1@4005,5095.3
  Bottom Layer w10: v1(3990,5065) 4004.7,5065 4035,5095.3 4160.9,5095.3 SBC.108@4175,5109.4
$1N245601: R40.1 SBC.35 | length 1077.9
  Top Layer w10: v1(4858,5638.7) 4861.6,5638.7 4864,5636.3 4883.2,5636.3 4918.5,5671.6 4941.7,5671.6 4958.2,5655.2 4958.2,5638.5 4960.4,5636.3 4968.9,5636.3 4973.7,5631.5 R40.1@5011.2,5631.5
  Bottom Layer w10: v1(4858,5638.7) 4880,5638.7 4887,5631.7 5423.2,5631.7 5478.1,5576.8 5478.1,5422.1 5485.8,5414.4 5497.5,5414.4 5507.5,5424.4 SBC.35@5553,5424.4
$1N245608: R39.1 SBC.36 | length 1074.1
  Top Layer w10: v1(4858,5608.7) 4861.6,5608.7 4868.6,5615.7 4885.2,5615.7 4925.1,5655.6 4935.1,5655.6 4942.2,5648.5 4942.2,5638.5 4940,5636.3 4928.1,5636.3 4921.6,5629.9 4921.6,5618 4912,5608.3 R39.1@4889.2,5608.3
  Bottom Layer w10: v1(4858,5608.7) 4880,5608.7 4887,5615.7 5416.6,5615.7 5462.1,5570.2 5462.1,5413.8 5479.2,5396.7 5495.8,5396.7 5507.5,5385 SBC.36@5553,5385
$1N245650: R38.1 SBC.37 | length 299.2
  Top Layer w10: R38.1@5289.7,5335 5298.1,5335 5316.5,5316.6 5316.5,5308.1 5321.7,5303 5403,5303 5424.7,5324.7 5424.8,5324.7 v1(5435.6,5335.5)
  Bottom Layer w10: v1(5435.6,5335.5) 5445.8,5345.7 SBC.37@5553,5345.7
$1N245689: R37.1 SBC.38 | length 289.6
  Top Layer w10: R37.1@5289.7,5274.3 5309.2,5274.3 5316.5,5281.6 ; 5318.8,5283.9 5316.5,5281.6 ; v1(5456.8,5314.2) 5451.2,5308.7 5431.3,5308.7 5409.6,5287 5321.7,5287 5316.5,5281.9 5316.5,5281.6
  Bottom Layer w10: v1(5456.8,5314.2) 5460.5,5318 5495.8,5318 5507.5,5306.3 SBC.38@5553,5306.3
$1N246123: R61.1 SBC.70 | length 8110.5
  Top Layer w10: v1(3170,4230) 3210,4190 3210,3660 v1(3280,3590) ; v1(3640,5130) v1(3640,5470) ; v1(4460,3620) 4650,3810 v1(4720,3810) ; v1(4760,6350) 4773.6,6336.4 4833.6,6336.4 v1(5120,6050) ; v1(4850,3850) 4940,3940 v1(4940,3960) ; v1(5077.7,5882.3) 5065.3,5870 5065.3,5766.9 5096.6,5735.6 R61.1@5106.3,5735.6 ; v1(5100,4233) 5107.4,4225.6 5121.5,4225.6 5131.5,4235.6 5142.7,4235.6 5144.5,4237.4 5163.5,4237.4 5165.3,4235.6 5197.1,4235.6 5204,4228.7 v1(5208.7,4228.7) ; v1(5120,4120) v1(5310,4120)
  Bottom Layer w10: v1(3170,4230) 3135,4265 3135,5035 3170,5070 3580,5070 v1(3640,5130) ; v1(3280,3590) 3390,3480 3550,3480 3680,3350 4050,3350 4320,3620 v1(4460,3620) ; v1(3640,5470) 3660,5470 3910,5720 3910,6220 4060,6370 4300,6370 4360,6430 4500,6430 4580,6350 v1(4760,6350) ; v1(4720,3810) 4810,3810 v1(4850,3850) ; v1(4940,3960) 5040,3960 5190,4110 5300,4110 v1(5310,4120) ; v1(5077.7,5882.3) 5077.7,5895 5055,5917.6 5055,5954.4 5077.7,5977 5077.7,6005.1 5093,6020.5 5093,6023 v1(5120,6050) ; SBC.70@5080.5,4322 5080.5,4249.5 5097,4233 v1(5100,4233) ; v1(5120,4120) 5204.8,4204.8 5204.8,4211.7 5208.7,4215.7 v1(5208.7,4228.7)
$1N246141: R60.1 SBC.68 | length 4080
  Top Layer w10: v1(4310,4430) 4310,4620 4227.6,4702.4 4200,4702.4 4200,5030 4207,5037 4207,5083.2 4228.3,5104.5 4274.5,5104.5 4280,5110 4280,5160 4289.8,5169.7 4289.8,5188.8 4280,5198.5 4280,5420 4310,5450 4310,5632.5 4313,5635.5 4313,5654.5 4310,5657.5 4310,5680 4350,5720 v1(4350,5780) ; v1(4310,5850) 4390,5850 4460,5920 4460,6240 4480,6260 4680,6260 4890,6050 4970,6050 5043.9,5976.1 5043.9,5793 R60.1@4986.6,5735.7 ; v1(4700,4390) 4749.3,4390 4769.3,4410 4822.5,4410 4827,4405.6 4844.4,4405.6 4883.2,4366.8 4883.2,4302 4901.4,4283.8 4966.2,4283.8 4970,4280 v1(5160,4280)
  Bottom Layer w10: v1(4310,4430) 4366.1,4430 4369.6,4426.5 4663.5,4426.5 v1(4700,4390) ; v1(4310,5850) 4310,5820 v1(4350,5780) ; SBC.68@5159.3,4322 5160,4321.3 v1(5160,4280)
$1N246151: R59.1 SBC.61 | length 2338.9
  Top Layer w10: v1(5519.1,4278) 5519.1,4230 v1(5520.6,4228.5) ; v1(6065,4790) 6080,4790 6215,4925 6289.9,4925 v1(6360.1,4995.2) ; v1(6401.1,5132.7) 6460.2,5191.8 6472.5,5191.8 6515,5234.3 v1(6515,5280) ; v1(6690,5610) 6695,5615 R59.1@6695,5665.3
  Bottom Layer w10: SBC.61@5435.5,4322.1 5435.5,4299.5 5457,4278 v1(5519.1,4278) ; v1(5520.6,4228.5) 5522.1,4230 5611.1,4230 5626.1,4215 5770,4215 5780,4225 5780,4465 5969.1,4654.1 5969.1,4695.3 5995.2,4721.3 6036.3,4721.3 6065,4750 v1(6065,4790) ; v1(6360.1,4995.2) 6401.1,5036.1 v1(6401.1,5132.7) ; v1(6515,5280) 6515,5410 6690,5585 v1(6690,5610)
$1N246158: R58.1 SBC.60 | length 111.9
  Top Layer w10: R58.1@5443.5,4444.3 5466.2,4444.3 v1(5479.6,4430.8)
  Bottom Layer w10: v1(5479.6,4430.8) 5486.9,4438.1 SBC.60@5546.8,4438.1
$1N246199: R57.1 SBC.59 | length 117.5
  Top Layer w10: R57.1@5444.5,4507.2 5448.1,4503.6 v1(5477.6,4503.6)
  Bottom Layer w10: v1(5477.6,4503.6) 5500.8,4480.4 SBC.59@5550.9,4480.4
$1N246204: R56.1 SBC.58 | length 119.2
  Top Layer w10: R56.1@5447.1,4565.1 v1(5475.5,4565.1)
  Bottom Layer w10: v1(5475.5,4565.1) 5500.6,4539.9 5506.5,4539.9 5513,4533.5 5513.3,4533.5 5528.7,4518.1 SBC.58@5546.8,4518.1
$1N246206: R55.1 SBC.65 | length 210.5
  Top Layer w10: v1(5274.4,4258.7) 5377.2,4258.7 5386.4,4259.5 R55.1@5408.1,4237.8 ; R55.1@5408.3,4225.3 R55.1@5408.3,4238
  Bottom Layer w10: v1(5274.4,4258.7) 5274.4,4307.8 SBC.65@5278.6,4312
$1N251051: R52.1 SBC.119 | length 1020.1
  Top Layer w10: R52.1@3859.7,4970 3780,5049.7 3780,5530 3825,5575 v1(4090,5575)
  Bottom Layer w10: v1(4090,5575) 4117.1,5575 4135,5557.1 4160.4,5557.1 SBC.119@4175,5542.5
$1N251056: R53.1 SBC.118 | length 1031
  Top Layer w10: v1(3815,5160) 3815,5495 3845,5525 v1(4090,5525) ; R53.1@3859.7,4910 3880,4910 v1(3895,4925)
  Bottom Layer w10: v1@3814.9,5162 3814.9,5003.9 v1@3896.1,4922.6 ; v1(4090,5525) 4111.9,5503.1 SBC.118@4175,5503.1
$1N256019: R51.1 SBC.113 | length 889.5
  Top Layer w10: R51.1@3859.7,4655 3965,4760.3 3965,5280 3980,5295 v1(4070,5295)
  Bottom Layer w10: v1(4070,5295) 4163.7,5295 SBC.113@4175,5306.3
$1N256024: R50.1 SBC.114 | length 884.3
  Top Layer w10: R50.1@3859.7,4715 3945,4800.3 3945,4845.5 3946,4846.5 3946,4946.1 3938.4,4953.7 3938.4,5056.4 3945,5063 3945,5315 3965,5335 v1(4090,5335)
  Bottom Layer w10: v1(4090,5335) 4100.7,5345.7 SBC.114@4175,5345.7
$1N256029: R49.1 SBC.115 | length 878.2
  Top Layer w10: R49.1@3859.7,4780 3932,4852.3 3932,4940.3 3911.9,4960.4 3911.9,5336.9 3960,5385 v1(4090,5385)
  Bottom Layer w10: v1(4090,5385) SBC.115@4175,5385
$1N256034: R48.1 SBC.117 | length 1001.5
  Top Layer w10: R48.1@3859.7,4845 3895,4880.3 3895,4892.5 3918,4915.5 3918,4934.5 3895,4957.5 3895,5005 3840,5060 3840,5440 3870,5470 v1(4095,5470)
  Bottom Layer w10: v1(4095,5470) 4168.8,5470 SBC.117@4175,5463.8
$1N256116: R44.1 SBC.110 | length 1053.5
  Top Layer w10: R44.1@4120,4274.7 4147,4301.7 4147,5092 4230,5175 4230,5184.9 v1(4245.6,5200.5)
  Bottom Layer w10: SBC.110@4175,5188.2 4233.3,5188.2 v1(4245.6,5200.5)
$1N256118: R43.1 SBC.109 | length 1063.1
  Top Layer w10: R43.1@4190,4274.7 4170,4294.7 4170,5092.4 4241.3,5163.7 4251.2,5163.7 v1(4266.8,5179.2)
  Bottom Layer w10: SBC.109@4175,5148.8 4236.3,5148.8 v1(4266.8,5179.2)
$1N256165: SBC.94 VCC_1.8.1 | length 96.9
  Bottom Layer w10: VCC_1.8.1@4084.1,4557.4 4088,4561.3 SBC.94@4179.4,4561.3
$1N256287: FLASH_CS0N.1 SBC.44 | length 99.8
  Top Layer w10: FLASH_CS0N.1@5475.3,5041.6 5479.7,5045.9 5479.7,5067.4 ; 5481.4,5068.7 5482.5,5069.8 v1(5507.7,5069.8)
  Bottom Layer w10: v1(5507.7,5069.8) 5508.4,5069.1 SBC.44@5552.8,5069.1
$1N256308: FLASH_RDY.1 SBC.45 | length 265.5
  Top Layer w10: v1(5466,5000.7) 5477.8,5012.5 5489.1,5012.5 5507.3,5030.7 FLASH_RDY.1@5619.9,5030.7
  Bottom Layer w10: v1(5466,5000.7) 5494.3,5029 SBC.45@5553.5,5029
$1N256614: MASKROM.1 R22.1 | length 190
  Top Layer w10: MASKROM.1@3631.3,4315 3700,4315 3715,4330 3715,4429.7 R22.1@3715.3,4430
$1N302380: R42.1 SBC.29 | length 394.4
  Top Layer w10: R42.1@5141.5,5644.3 5289.5,5644.3 5329.3,5684.1 v1(5329.3,5758.9)
  Bottom Layer w10: v1(5329.3,5758.9) 5385.9,5758.9 5396.1,5748.8 SBC.29@5396.1,5704.4
$1N313637: C37.1 RTC.5 RTC.14 | length 936.8
  Top Layer w10: RTC.14@6631,4925 6636,4930 v1(6730,4930) ; RTC.5@7009,5025 v1(7060,5025)
  Bottom Layer w10: C37.1@6680,5052.4 6679.9,5052.3 6679.9,4982.4 v1@6732.3,4930 ; v1(6730,4930) v1@6732.3,4930 ; v1(7060,5025) 7060,5007.5 7083,4984.5 7083,4965.5 7069.5,4952 6997,4952 6880,4835 6880,4782.3 6864.8,4782.3 6849.5,4767 6830.5,4767 6817,4780.5 6817,4845.3 v1@6732.3,4930
$1N313732: BAT+.1 C34.1 RTC.15 | length 198.9
  Top Layer w10: v1(6570,4900) 6595,4875 RTC.15@6631,4875
  Bottom Layer w10: v1(6570,4900) C34.1@6570,4952.4 6627.6,4952.4 BAT+.1@6640,4940
AMP_EN: M1.5 SBC.9 | length 983.3
  Top Layer w10: v1(5144.7,5834.7) 5159.8,5819.5 v1(5223.7,5819.5)
  Bottom Layer w10: SBC.9@4608,5716.1 4608,5738.2 4619.6,5749.8 4669.5,5749.8 4754.3,5834.7 v1(5144.7,5834.7) ; v1(5223.7,5819.5) 5242.3,5801 5378.2,5801 5392.2,5814.9 M1.5@5392.2,5932.2
BCLK: M1.2 R61.2 Top_PCB.5 | length 2645.6
  Top Layer w10: R61.2@5104.9,5800.2 5104.9,5930.6 M1.2@5099.5,5936 5180.8,6017.3 v1(5667.3,6017.3) ; v1(6068.5,6021.8) 6297.6,6021.8 6329.4,5990 6395.2,5990 6412.1,5973.1 6473.5,5973.1 6490.4,5990 6536.6,5990 6546.3,5980.3 6612.5,5980.3 v1(6620,5987.7)
  Bottom Layer w10: v1(5667.3,6017.3) 5739.1,6017.3 5748.6,6026.9 5767.6,6026.9 5777.2,6017.3 6064,6017.3 v1(6068.5,6021.8) ; v1(6620,5987.7) 6626.6,5987.7 6644.6,5969.7 6694.3,5969.7 6696.3,5967.8 6819.5,5967.8 6828.4,5976.7 7010.8,5976.7 7029.7,5957.7 7029.7,5658.5 7012.4,5641.2 Top_PCB.5@6856.3,5641.2
BUZZER: BUZZER.1 SBC.4 | length 243.3
  Top Layer w10: v1(4400,5615) 4405,5610 BUZZER.1@4405,5463.4
  Bottom Layer w10: v1(4400,5615) 4400,5688.8 SBC.4@4411.2,5700
CH340-2_D+: CH340K-2.1 USB_SWITCH.9 | length 1494.4
  Top Layer w10: v1(4550,4725) 4602.3,4725 USB_SWITCH.9@4602.5,4725.1 ; v1(5417,4783) 5417,4788 5424,4795 5424,4811.6 5478.5,4866.1 5726,4866.1 5742.5,4849.7 5742.5,4833.1 5754.1,4821.4 CH340K-2.1@5754.1,4781.9
  Bottom Layer w10: v1(4550,4725) 4576,4751 4652.5,4751 4655,4753.6 4674.1,4753.6 4676.6,4751 4701.6,4751 4761.6,4691 5388,4691 5429.2,4732.2 5429.2,4748.8 5417,4761 v1(5417,4783)
CH340-2_D-: CH340K-2.2 USB_SWITCH.8 | length 1364.1
  Top Layer w10: USB_SWITCH.8@4602.5,4750.1 4644.9,4750.1 v1(4664.5,4730.6) ; v1(5457.4,4776.4) 5457.4,4777.6 5440,4795 5440,4805 5485.1,4850.1 5719.4,4850.1 5726.5,4843.1 5726.5,4833.1 5714.8,4821.4 CH340K-2.2@5714.8,4781.9
  Bottom Layer w10: v1(4664.5,4730.6) 4669,4735 4695,4735 4755,4675 5394.6,4675 5445.2,4725.6 5445.2,4742.2 5457.4,4754.4 v1(5457.4,4776.4)
CH340_D+: CH340K.1 USB_SWITCH.11 | length 2580.9
  Top Layer w10: v1(4486.5,4672.6) 4508.5,4672.6 4515.5,4679.6 4553.5,4679.6 4558,4675.1 USB_SWITCH.11@4602.5,4675.1 ; v1(5283.7,4527.3) 5290.7,4534.3 5296,4534.3 5309.5,4547.8 5309.5,4556.7 5370.5,4617.8 5370.5,4721.1 5377.5,4728.1 v1(5377.5,4737) ; v1(5492.1,4926.2) 5507.6,4941.8 5507.6,4951.7 5514.7,4958.8 5524.7,4958.8 5580.2,4903.2 5632.9,4903.2 5639.7,4910.1 v1(5674.4,4910.1) ; v1(6104.9,4945.9) 6120.5,4961.5 6120.5,4971.4 6132.2,4983.2 6132.2,5232.3 CH340K.1@6140,5240.1
  Bottom Layer w10: v1(4486.5,4672.6) 4508.5,4672.6 4515.5,4679.6 4691.9,4679.6 4775.2,4596.3 4967,4596.3 4974,4589.2 4974,4530.1 5021,4483.1 5242,4483.1 5283.7,4524.8 v1(5283.7,4527.3) ; v1(5377.5,4737) 5377.5,4759 5370.5,4766 5370.5,4814.6 5466.6,4910.7 5476.5,4910.7 v1(5492.1,4926.2) ; v1(5674.4,4910.1) 5697.7,4910.1 5706.6,4919 5706.6,4932 5720.1,4945.5 5739.1,4945.5 5781.3,4903.2 6052.3,4903.2 6079.4,4930.4 6089.3,4930.4 v1(6104.9,4945.9)
CH340_D-: CH340K.2 USB_SWITCH.10 | length 2626.6
  Top Layer w10: v1(4486.5,4702.6) 4508.5,4702.6 4515.5,4695.6 4553.5,4695.6 4558,4700.1 USB_SWITCH.10@4602.5,4700.1 ; v1(5286.5,4557.3) 5302,4572.9 5303,4572.9 5354.5,4624.4 5354.5,4721.1 5347.5,4728.1 v1(5347.5,4737) ; v1(5470.8,4947.4) 5486.4,4963 5496.3,4963 5508.1,4974.8 5531.3,4974.8 5586.8,4919.2 5619.8,4919.2 5640.6,4940.1 v1(5674.4,4940.1) ; v1(6083.7,4967.2) 6099.3,4982.7 6109.2,4982.7 6116.2,4989.8 6116.2,5206.9 6099.4,5223.7 6099.4,5256.4 6122.5,5279.4 CH340K.2@6140,5279.4
  Bottom Layer w10: v1(4486.5,4702.6) 4508.5,4702.6 4515.5,4695.6 4698.5,4695.6 4781.9,4612.3 4973.6,4612.3 4990,4595.8 4990,4536.7 5027.6,4499.1 5235.4,4499.1 5260.7,4524.5 5260.7,4536.8 5281.2,4557.3 v1(5286.5,4557.3) ; v1(5347.5,4737) 5347.5,4759 5354.5,4766 5354.5,4821.2 5455.3,4922 5455.3,4931.9 v1(5470.8,4947.4) ; v1(5674.4,4940.1) 5683.5,4940.1 5690.6,4933 5690.6,4938.6 5713.4,4961.5 5745.7,4961.5 5788,4919.2 6045.7,4919.2 6068.1,4941.7 6068.1,4951.6 v1(6083.7,4967.2)
D+: Bottom_PCB.2 USB-C2.A6 USB-C2.B6 USB_SWITCH.16 | length 3183.1
  Top Layer w10: v1(4808.8,4387) 4808.8,4375 4801.8,4368 4801.8,4288.3 4821.3,4268.8 4831.3,4268.8 4831.5,4268.6 v1(4840.8,4268.6) ; USB_SWITCH.16@4809.2,4625.1 4853.7,4625.1 4858.2,4620.6 4874.8,4620.6 4891.2,4604.2 4891.2,4580.9 4874.8,4564.5 4869.9,4564.5 4849.9,4544.6 4849.9,4534.7 v1(4834.4,4519.1) ; v1(5455.2,3941.3) 5433.2,3941.3 5426.2,3948.3 5353.6,3948.3 5207.5,4094.5 4977,4094.5 v1(4923.3,4148.2) 4923.3,4154.4 4936.1,4167.1 4981.5,4167.1 4990.6,4158 5920.8,4158 5954.4,4191.5 v1@5955.8,4191.5 ; v1(5962,4247.6) 5983.3,4247.6 5991,4239.9 6059.3,4239.9 6266.6,4447.1 6283.2,4447.1 6285,4449 USB-C2.B6@6317.1,4449 6317.4,4448.6 6354,4448.6 6362.1,4440.5 6362.1,4416.7 6352.8,4407.5 6319.8,4407.5 USB-C2.A6@6319.4,4407.8
  Bottom Layer w10: v1(4808.8,4387) 4808.8,4419 4801.8,4426.1 4801.8,4496.5 4808.9,4503.5 4818.8,4503.5 v1(4834.4,4519.1) ; v1(4840.8,4268.6) 4882.3,4268.6 4884.6,4266.3 4901.2,4266.3 4917.7,4249.9 4917.7,4196.8 4923.3,4191.2 v1(4923.3,4148.2) ; v1(5455.2,3941.3) 5477.2,3941.3 5484.2,3948.3 5494.2,3948.3 5501.3,3941.2 5501.3,3931.2 5481.9,3911.8 5481.9,3876.4 5509.2,3849.1 Bottom_PCB.2@5509.2,3824.5 ; v1(5955.2,4192.2) 5962,4198.9 v1(5962,4247.6)
D-: Bottom_PCB.3 USB-C2.A7 USB-C2.B7 USB_SWITCH.15 | length 3393.3
  Top Layer w10: v1(4778.8,4387) 4778.8,4375 4785.8,4368 4785.8,4281.5 4828.9,4238.5 v1(4847.3,4238.5) ; USB_SWITCH.15@4809.2,4600.1 4853.7,4600.1 4858.2,4604.6 4868.2,4604.6 4875.2,4597.6 4875.2,4587.6 4868.2,4580.5 4863.2,4580.5 4838.6,4555.9 4828.7,4555.9 v1(4813.2,4540.3) ; v1@5455.8,3971.4 5462.9,3964.3 5464.7,3964.3 5478.2,3950.8 5478.2,3931.8 5464.4,3918 5120.9,3918 4900.3,4138.6 4900.3,4139.4 v1(4893.3,4146.4) 4893.3,4163.7 4917.1,4187.4 4983.8,4187.4 4993.8,4177.4 5900.2,4177.4 5940.3,4217.6 5984.7,4217.6 5991,4223.9 6065.9,4223.9 6273.2,4431.1 6283.2,4431.1 6285,4429.3 ; v1(5468.6,3777.4) 5507.2,3816.1 v1@5507.2,3888 ; USB-C2.B7@6306.7,4390.9 6306.3,4390.9 6305.1,4389.7 6285.2,4389.7 6276.4,4398.5 6276.4,4420.7 6285,4429.3 ; USB-C2.A7@6317.1,4429.3 USB-C2.A7@6316.7,4429.3 ; 6285,4429.3 USB-C2.A7@6316.7,4429.3 ; 6285,4429.3 6285.7,4429.9 6316.1,4429.9 USB-C2.A7@6316.7,4429.3
  Bottom Layer w10: v1(4778.8,4387) 4778.8,4419.1 4785.8,4426.1 4785.8,4503.1 4797.6,4514.8 4797.6,4524.7 v1(4813.2,4540.3) ; v1(4847.3,4238.5) 4862.7,4238.5 4872.7,4248.5 4894.6,4248.5 4901.7,4241.4 4901.7,4196.8 4893.3,4188.4 v1(4893.3,4146.4) ; v1(5455.2,3971.3) 5477.2,3971.3 5484.2,3964.3 5500.8,3964.3 5517.3,3947.9 5517.3,3924.6 5497.9,3905.2 5497.9,3896.2 5504.9,3889.1 v1(5507.9,3889.1) ; v1(5468.6,3777.4) 5469.3,3778.2 Bottom_PCB.3@5469.3,3824.3
DTR: CH340K.4 Q2.2 Q3.1 | length 1046.4
  Top Layer w10: CH340K.4@6131.1,5361.2 6597.7,5361.2 v1(6615.7,5343.2) ; Q3.1@6763.4,5242.6 6768.2,5242.6 6799.2,5273.5 6799.2,5549.5 Q2.2@6771.1,5577.6
  Bottom Layer w10: v1(6615.7,5343.2) 6785.4,5343.2 v1(6799.8,5357.6)
E-INK_BUSY: E-INK.9 SBC.1 | length 2976.2
  Top Layer w10: E-INK.9@3430.7,3873.9 3474.8,3873.9 v1(3485.4,3884.6) ; v1(3710,4155) 3620,4155 3450,4325 3450,5465 3645,5660 3865,5660 3945,5740 4195,5740 v1(4290,5645)
  Bottom Layer w10: v1(3485.4,3884.6) 3485.4,3930.4 3509.5,3954.5 3509.5,4012 3523,4025.5 3580.5,4025.5 v1(3710,4155) ; v1(4290,5645) 4293.1,5648.1 SBC.1@4293.1,5700
E-INK_CLK: E-INK.13 SBC.41 | length 6073.8
  Top Layer w10: v1(3330,3820) 3354.8,3795.2 E-INK.13@3430.7,3795.2 ; v1(3849.1,4125) 3947.3,4125 v1(3953.9,4118.4) ; v1(4003.8,4180.9) 4061.2,4123.5 v1(4073,4123.5) ; v1(4222.2,4242.7) 4270.6,4194.3 v1(4305,4194.3) ; v1(4447.5,4228) 4447.5,4539.1 v1(4450.7,4542.4) ; v1(4560.7,5285.1) 4865.6,4980.2 4908.2,4980.2 v1(4935.3,5007.3) ; v1(5105.8,4847.1) 5132.6,4847.1 5136.2,4850.7 5155.3,4850.7 5158.9,4847.1 5169,4847.1 5181.1,4859.1 5421.2,4859.1 v1(5421.2,4920.5) ; v1(5405.1,5233.6) 5491.6,5233.6 5644.8,5386.8 5644.8,5432.2 5657.5,5444.9 5657.5,5475.5 5644.8,5488.2 v1(5644.8,5574.6)
  Bottom Layer w10: v1@3330.3,3814.6 3242.9,3902 3242.9,4174 3320.6,4251.7 3782.9,4251.7 3849.1,4185.5 v1(3849.1,4125) ; v1(3953.9,4118.4) 3953.9,4128.7 v1@3999.9,4174.6 ; v1@3999.4,4176.5 v1(4003.8,4180.9) ; v1@4072.7,4123.6 4124.8,4175.6 4155.2,4175.6 v1(4222.2,4242.7) ; v1(4305,4194.3) 4305.6,4193.7 4310.4,4193.7 4320.3,4203.5 4320.3,4207.3 4333.7,4220.8 4337.5,4220.8 4377.7,4261 4412.1,4261 4445.1,4228 v1(4447.5,4228) ; v1(4450.7,4542.4) 4450.7,4656.1 4449.5,4657.3 4449.5,4718 4450.7,4719.2 4450.7,4911.5 4587.8,5048.5 4587.8,5258 v1(4560.7,5285.1) ; v1(4935.3,5007.3) 4827.8,4899.7 4827.8,4792.2 4896,4724 4994,4724 5105.8,4835.8 v1(5105.8,4847.1) ; v1(5405.1,5233.6) 5393,5221.5 5393,5163.4 5327.7,5098.1 5327.7,4923.8 5331.1,4920.5 5349.4,4920.5 5376.1,4893.7 5395.1,4893.7 5421.2,4919.8 v1(5421.2,4920.5) ; SBC.41@5553,5188.2 5599.4,5188.2 5625.1,5213.9 5625.1,5412.5 5657.5,5444.9 5657.5,5475.5 5644.8,5488.2 v1(5644.8,5574.6)
E-INK_CS: E-INK.12 SBC.42 | length 5731.8
  Top Layer w10: v1(3365,3830) 3380.2,3814.8 E-INK.12@3430.7,3814.8 ; v1(3626.5,4223.6) 3638.5,4235.5 3889.7,4235.5 4043.8,4081.4 4045.2,4081.4 v1@4062.6,4064.1 ; v1(4113.4,4127.2) 4136.2,4127.2 4171.1,4092.3 v1(4180.2,4092.3) ; v1@4342.6,4199.3 4384.3,4241.1 4412.2,4241.1 4412.2,4541.5 v1(4411.4,4542.4) ; v1(4532.9,5257.2) 4847.1,4943 4872.1,4943 4883.4,4954.3 4938,4954.3 v1(4963.2,4979.4) ; v1(5105.8,4906.4) 5375.3,4906.4 v1(5385.6,4916.7) ; v1(5416,5199.9) 5421.7,5194.2 5507.9,5194.2 5684.2,5370.5 5684.2,5546.2 5677.8,5552.6 v1(5677.8,5574.6)
  Bottom Layer w10: v1@3366.2,3828.8 3268.2,3926.8 3268.2,4162.6 3329.2,4223.6 v1(3626.5,4223.6) ; v1(4063.4,4062.3) 4063.4,4075.3 v1@4114.4,4126.2 ; v1@4181.4,4094.6 4216.1,4129.3 4219.3,4129.3 ; 4217.7,4130.9 4233.9,4147.2 ; 4235.7,4145.5 4266.2,4145.5 4279.7,4158.9 ; 4279.7,4158.1 4303.5,4158.1 v1(4343.2,4197.8) ; v1(4411.4,4542.4) 4411.4,4927.8 4548.4,5064.8 4548.4,5241.7 v1(4532.9,5257.2) ; v1(4963.2,4979.4) 4850,4866.3 4850,4790 4890,4750 4976.2,4750 5105.8,4879.6 v1(5105.8,4906.4) ; v1(5385.6,4916.7) 5374.2,4916.7 5367.1,4923.8 5367.1,5117.7 5416,5166.6 v1(5416,5199.9) ; SBC.42@5553,5148.8 5579.9,5148.8 5630.9,5199.9 5650,5199.9 5658.3,5191.5 5673.7,5191.5 5684.2,5202 5684.2,5568.2 v1(5677.8,5574.6)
